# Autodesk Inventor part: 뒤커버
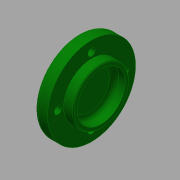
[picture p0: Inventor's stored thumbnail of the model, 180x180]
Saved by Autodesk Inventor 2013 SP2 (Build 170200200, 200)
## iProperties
Created: 2015-12
Part Number: 뒤커버
Material: 알루미늄 6061
Document SubType Name: Modeling
Designer: mduedu
Density: 2.71 g/cm^3
Author: mduedu
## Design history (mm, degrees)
sketch "스케치1"
  geometry: L1 (0, 0)-(14, 0); L2 (14, 0)-(14, 17.5); L3 (14, 17.5)-(8, 17.5); L4 (8, 17.5)-(8, 27.5); L5 (8, 27.5)-(0, 27.5); L6 (0, 27.5)-(0, 0)
  constraints: 12 end point, 4 parallel, 1 horizontal, 1 perpendicular
  dimensions: "d0" = 14 distance between parallel lines of L2 L6; "d2" = 8 distance of L4.end L5.end; "d3" = 55 diameter of L5 L1; "d4" = 35 diameter of L3 L1
revolve "회전1" sketch "스케치1" stored, may be unused: angle "d5" = 90 deg
hole "구멍1" diameter "d8" = 30; stored, may be unused: countersink angle "d12" = 90 deg, drill point angle "d14" = 0 deg; dims "d9" = 6, "d10" = 4, "d11" = 2, "d13" = 7, "d39" = 10, "d40" = 10
fillet "모깎기3" dims "d38" = 2
fillet "모깎기4" dims "d41" = 3
chamfer "모따기2" distance "d42" = 0.5; stored, may be unused: second distance "d43" = 2, angle "d44" = 45 deg
sketch "스케치2" dims "d45" = 42
  geometry: 6 further points
  constraints: 2 vertical alignment, 1 coincident, 7 other
  dimensions: "d48" = 360 deg dimension on point (0, 0) point (0, 21) (derived)
sketch "스케치3"
  geometry: 4 further points
hole "구멍4" sketch "스케치3" at (-21, 0), (0, -21), (21, 0), (0, 21) diameter "d50" = 4.5; stored, may be unused: countersink angle "d54" = 90 deg, drill point angle "d56" = 0 deg; dims "d51" = 6, "d52" = 8, "d53" = 4.6, "d55" = 8
node "솔리드1"
